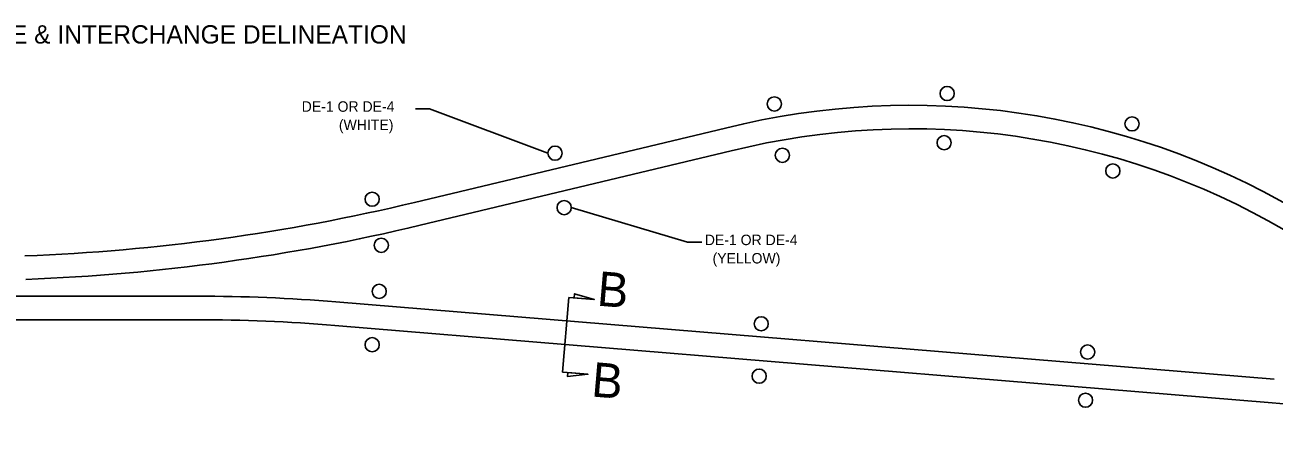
# Model space of a CAD drawing. Extents: x -0.14 to 2.7, y -0.05 to 1.78.
# Drawn here: x 1.18 to 2.172, y 0.811 to 1.136 of the extents above; entities that cross this region are included whole.
import ezdxf

# ---------------------------------------------------------------- set-up
doc = ezdxf.new("R2010")
doc.units = 0
doc.layers.add('CT_CSHT_GeneralLabel', color=7, linetype='Continuous')

msp = doc.modelspace()

# ---------------------------------------------------------------- linework, layer by layer
at = {"layer": 'CT_CSHT_GeneralLabel'}
for p, q in [((1.49008, 1.06905), (1.50137, 1.06905)), ((1.50137, 1.06905), (1.59539, 1.03377)), ((1.48945, 0.99459), (1.7364, 1.05375)), ((1.49381, 0.97641), (1.74075, 1.03557)), ((1.7062, 0.96298), (1.61388, 0.99049)), ((1.71749, 0.96298), (1.7062, 0.96298)), ((0.6263, 0.92006), (1.31714, 0.92006)), ((1.42706, 0.91553), (2.17194, 0.85398)), ((1.60704, 0.85973), (1.61206, 0.91913)), ((1.61206, 0.91913), (1.63212, 0.91743)), ((1.61621, 0.91871), (1.61649, 0.92198)), ((1.63212, 0.91743), (1.61649, 0.92198)), ((1.31635, 0.90136), (1.15299, 0.90136)), ((1.42625, 0.89683), (2.17041, 0.83535)), ((1.60704, 0.85973), (1.6271, 0.85803)), ((1.61093, 0.85611), (1.61121, 0.85938)), ((1.61093, 0.85611), (1.6271, 0.85803))]:
    msp.add_line(p, q, dxfattribs=at)
for points in [[(1.61621, 0.91871), (1.61649, 0.92198), (1.63212, 0.91743)], [(1.61121, 0.85938), (1.61093, 0.85611), (1.6271, 0.85803)]]:
    msp.add_lwpolyline(points, close=True, dxfattribs=at)
for centre in [(1.91237, 1.08122), (1.77515, 1.0729), (2.05921, 1.05708), (1.90996, 1.0421), (1.60102, 1.03377), (1.78157, 1.03211), (2.04397, 1.01962), (1.45578, 0.99715), (1.60824, 0.99049), (1.463, 0.96052), (1.4614, 0.92389), (1.76472, 0.89809), (1.45578, 0.88144), (2.02391, 0.87561), (1.76312, 0.85646), (2.0223, 0.83732)]:
    msp.add_circle(centre, 0.00563, dxfattribs=at)
for centre, radius, start, end in [((1.88334, 0.46588), 0.60596, 59.66665, 104.0339), ((1.88334, 0.46588), 0.58726, 59.66665, 104.0339), ((1.12038, 2.53482), 1.58384, 272.1604, 283.47505), ((1.12038, 2.53482), 1.60253, 272.1604, 283.47505), ((1.31714, -0.41534), 1.33539, 85.27877, 90), ((1.31635, -0.43403), 1.33539, 85.27929, 90), ((1.952, -1.80773), 2.65209, 80.93068, 85.27604)]:
    msp.add_arc(centre, radius, start, end, dxfattribs=at)

# ---------------------------------------------------------------- texts
for s, height, p in [('TYPICAL MAINLINE & INTERCHANGE DELINEATION', 0.0145833, (1.00314, 1.12095)), ('DE-1 OR DE-4', 0.0083333, (1.39982, 1.0667)), ('  (WHITE)', 0.008333, (1.42317, 1.05212)), ('DE-1 OR DE-4', 0.0083333, (1.71992, 0.96064)), ('  (YELLOW)', 0.008333, (1.71992, 0.94605))]:
    msp.add_text(s, height=height, dxfattribs=at).set_placement(p)
for p in [(1.63379, 0.91262), (1.62932, 0.84036)]:
    msp.add_text('B', height=0.02742, rotation=355.17397, dxfattribs=at).set_placement(p)

doc.saveas('drawing.dxf')
